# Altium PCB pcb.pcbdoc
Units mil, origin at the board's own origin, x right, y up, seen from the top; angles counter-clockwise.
Board outline 1284.99 x 1174.13 mil, 2 copper layers (Top Layer, Bottom Layer); 2 components, 0 nets, 8 pads, 0 vias.
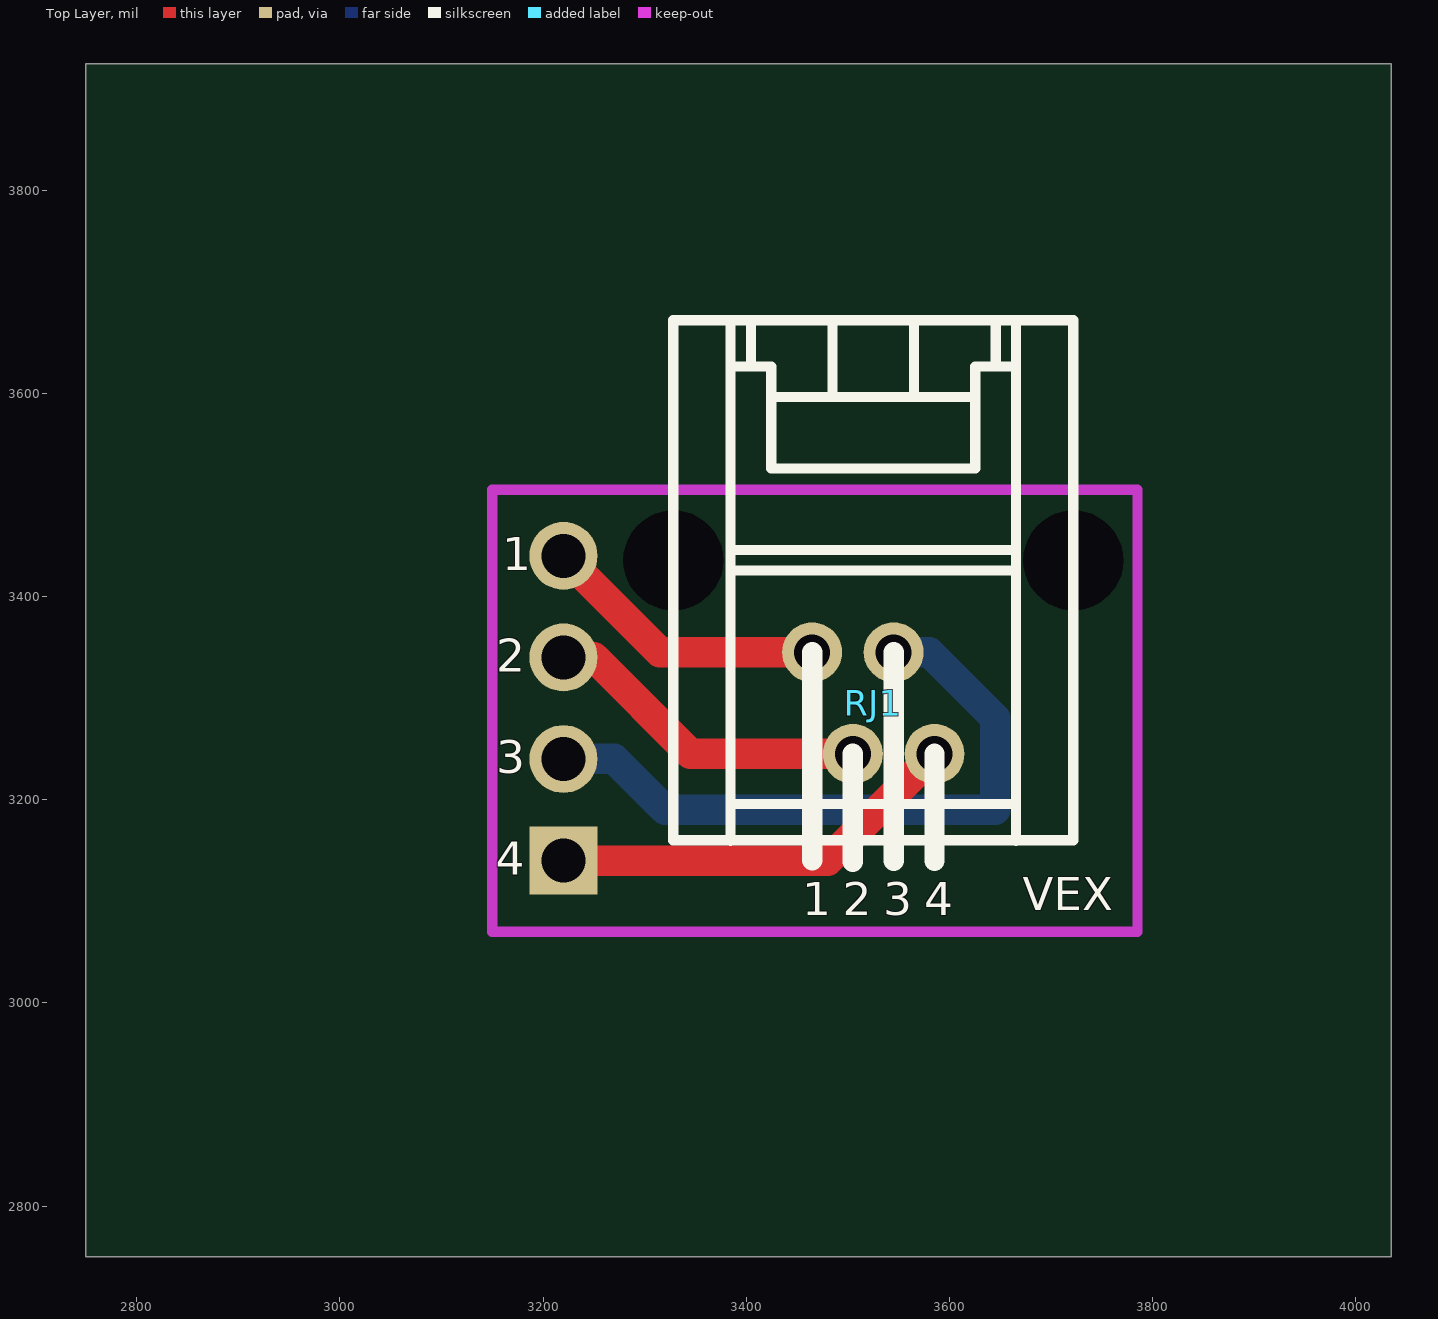
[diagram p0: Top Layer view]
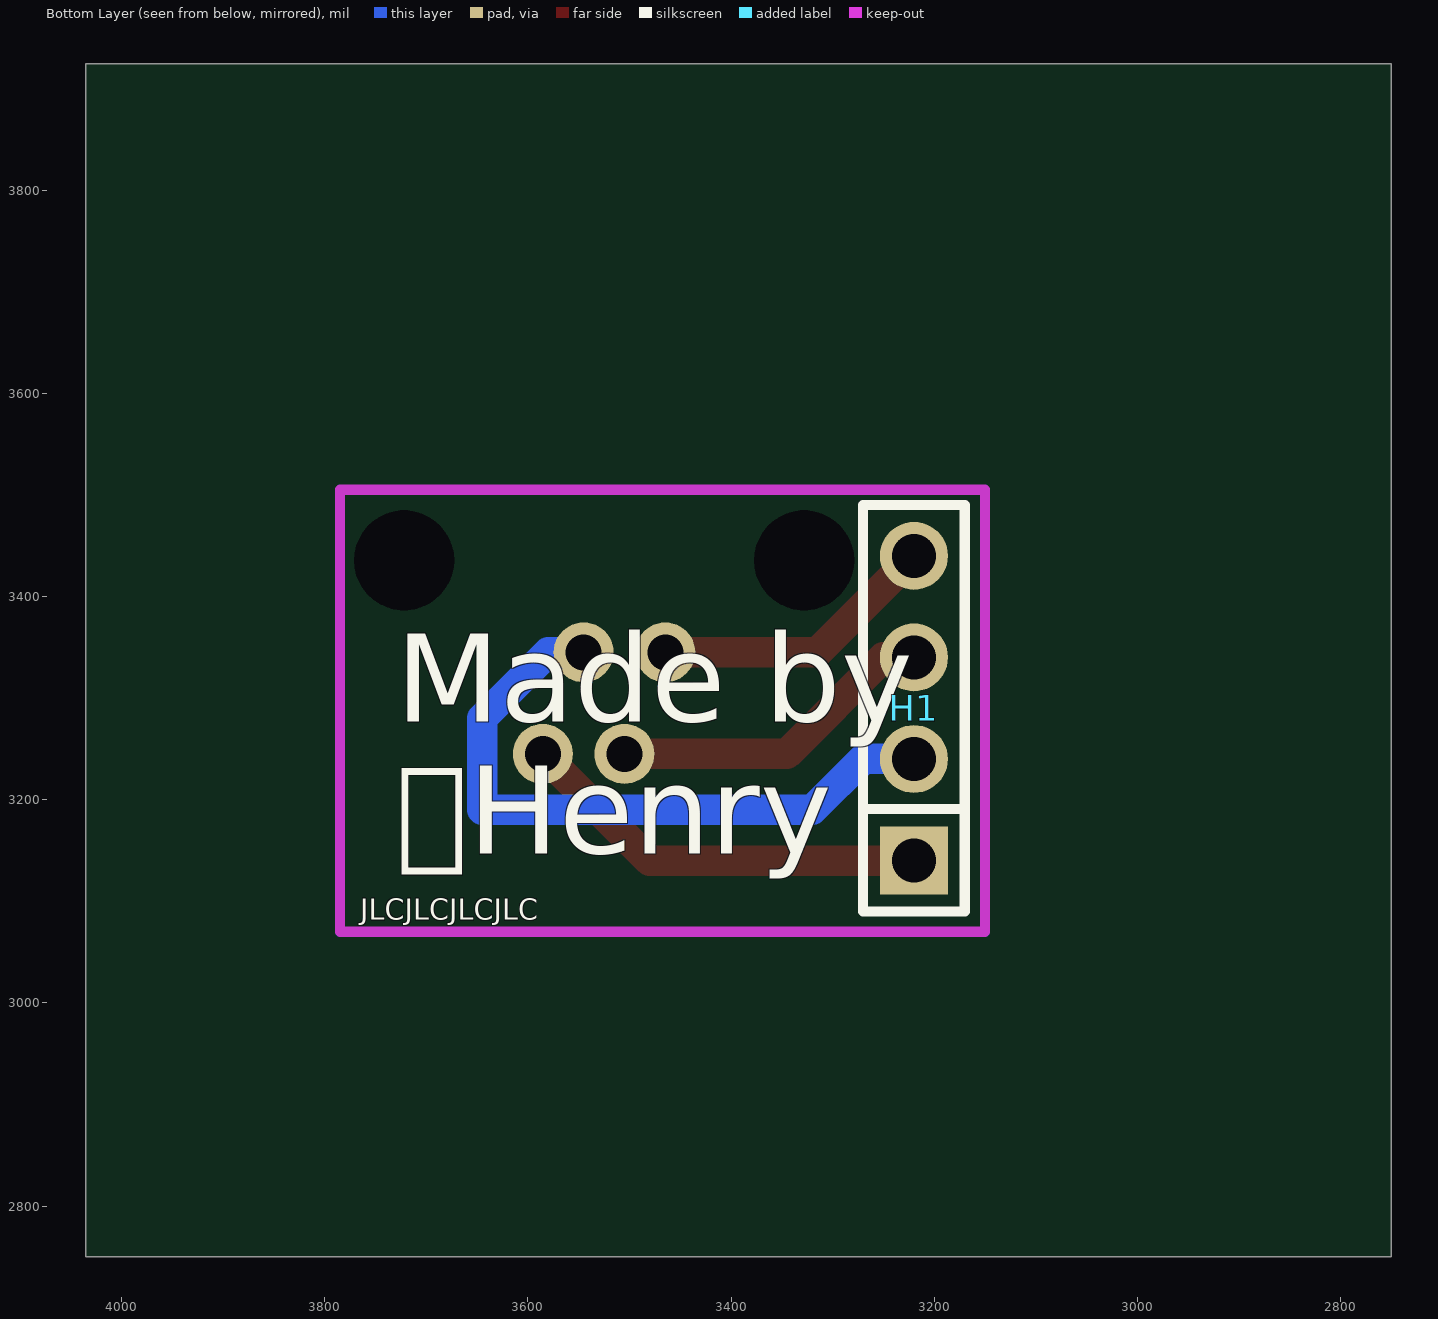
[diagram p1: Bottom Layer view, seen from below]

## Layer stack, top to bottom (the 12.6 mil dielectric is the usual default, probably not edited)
Top Layer: signal copper (thickness not stored)
Dielectric: dielectric 12.6, FR-4, Dk 4.8
Bottom Layer: signal copper (thickness not stored)

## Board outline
4034.99,2750 2750,2750 2750,3924.13 4034.99,3924.13

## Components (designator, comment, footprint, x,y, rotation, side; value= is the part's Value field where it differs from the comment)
H1 "KH-2.54PH180-1X4P-L11.5" HDR-TH_4P-P2.54-V-M 3220,3290 r90 bottom
RJ1 "R-RJ11R04P-A802" RJ11-TH_616-PCB-4P4C-90 3525,3295 r90 top

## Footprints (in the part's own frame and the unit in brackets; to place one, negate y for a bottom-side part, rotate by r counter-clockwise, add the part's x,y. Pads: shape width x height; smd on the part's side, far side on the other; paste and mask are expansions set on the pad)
HDR-TH_4P-P2.54-V-M [mm]
  rect 1.7x1.7 hole 1.1: 1(-3.81,0)
  round 1.7 hole 1.1: 2(-1.27,0) 3(1.27,0) 4(3.81,0)
  silkscreen extent -5.08,-1.27 5.08,1.27
RJ11-TH_616-PCB-4P4C-90 [mm]
  round 1.5 hole 0.9: 1(1.27,1.53) 2(-1.27,0.51) 3(1.27,-0.51) 4(-1.27,-1.53)
  Multi-Layer board cut-out: 3.57,3.75 4.112,3.874 4.547,4.221 4.789,4.722 4.789,5.278 4.547,5.779 4.112,6.126 3.57,6.25 3.57,6.25 3.028,6.126 2.593,5.779 2.351,5.278 2.351,4.722 2.593,4.221 3.028,3.874 3.57,3.75
  Multi-Layer board cut-out: 3.57,-6.25 4.112,-6.126 4.547,-5.779 4.789,-5.278 4.789,-4.722 4.547,-4.22 4.112,-3.874 3.57,-3.75 3.57,-3.75 3.028,-3.874 2.593,-4.22 2.351,-4.722 2.351,-5.278 2.593,-5.779 3.028,-6.126 3.57,-6.25
  silkscreen extent -3.44,-5 9.57,5

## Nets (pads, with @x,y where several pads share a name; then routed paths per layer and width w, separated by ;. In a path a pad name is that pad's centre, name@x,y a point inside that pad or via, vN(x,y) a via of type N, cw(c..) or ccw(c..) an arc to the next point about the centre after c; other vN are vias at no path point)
pads on no net: H1.1 H1.2 H1.3 H1.4 RJ1.1 RJ1.2 RJ1.3 RJ1.4
copper on no net: | length 1679.7
  Top Layer w30: 3220,3140 3480.24,3140 3585.24,3245 ; 3220,3340 3250,3340 3345,3245 3504.91,3245 ; 3220,3440 3315,3345 3464.76,3345
  Bottom Layer w30: 3220,3240 3270,3240 3320,3190 3645,3190 3645,3280 3580,3345 3545.07,3345

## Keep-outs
Board Outline Layer:
  lines w10: 3149.99,3070 3784.99,3070 3784.99,3505 3149.99,3505 3149.99,3070

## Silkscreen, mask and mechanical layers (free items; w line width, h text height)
Top Silkscreen Layer:
  lines w20: 3464.76,3345 3465,3140 ; 3504.91,3138.59 3504.91,3245 ; 3545.07,3139.56 3545.07,3345 ; 3585.24,3139.56 3585.24,3245
  text "1" at 3160,3425.98 h32.69
  text "2" at 3153.95,3325.98 h32.69
  text "3" at 3153.95,3225.98 h32.69
  text "4" at 3153.25,3125.98 h32.69
  text "VEX" at 3672.23,3091.1 h32.45
  text "1" at 3455,3085.98 h32.69
  text "2" at 3495,3085.98 h32.69
  text "3" at 3535,3085.98 h32.69
  text "4" at 3575,3085.98 h32.69
Bottom Silkscreen Layer:
  text "Made by /  Henry" at 3729.84,3146.64 h86.82
  text "JLCJLCJLCJLC" at 3765.18,3081.99 h20.44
